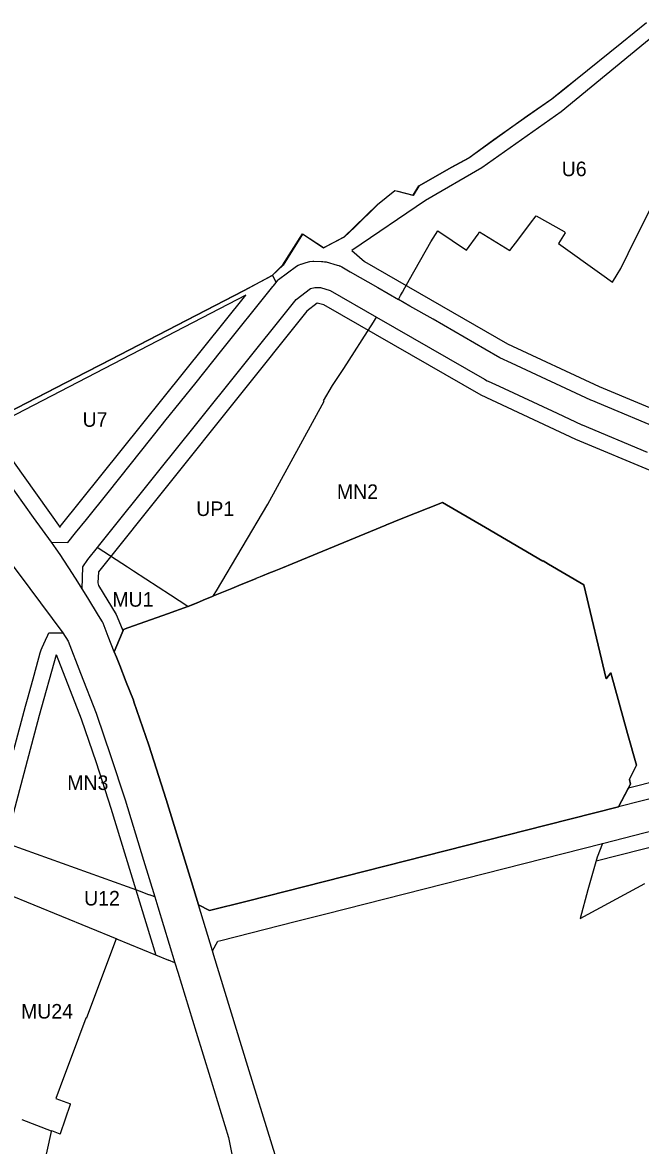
# Model space of a CAD drawing. Extents: x 7428103 to 7431580, y 5545880 to 5549002.
# Drawn here: x 7429328.8 to 7429564.3, y 5548288 to 5548716 of the extents above; entities that cross this region are included whole.
import ezdxf

# ---------------------------------------------------------------- set-up
doc = ezdxf.new("R2010")
doc.units = 0
for name, color, linetype in [('CZ_L_granica obszaru objętego planem', 7, 'Continuous'), ('CZ_L_linie rozgraniczające tereny o różnym przeznaczeniu oraz różnych warunkach ich zabudowy i zagospodarowania', 7, 'Continuous'), ('CZ_L_maksymalne nieprzekraczalne linie zabudowy', 7, 'Continuous'), ('CZ_L_opisy_linie rozgraniczające tereny o różnym przeznaczeniu oraz różnych warunkach ich zabudowy i zagospodarowania', 7, 'Continuous'), ('WYROK_NSA', 7, 'Continuous')]:
    doc.layers.add(name, color=color, linetype=linetype)

msp = doc.modelspace()

# ---------------------------------------------------------------- linework, layer by layer
at = {"layer": 'CZ_L_granica obszaru objętego planem'}
for p, q in [((7429557.12, 5548708.39), (7429566.53, 5548715.99)), ((7429539.52, 5548694.12), (7429557.12, 5548708.39)), ((7429535.35, 5548690.75), (7429539.52, 5548694.12)), ((7429530.54, 5548686.85), (7429535.35, 5548690.75)), ((7429521.16, 5548680.39), (7429530.54, 5548686.85)), ((7429508.43, 5548671.31), (7429521.16, 5548680.39)), ((7429498.88, 5548664.38), (7429508.43, 5548671.31)), ((7429492.26, 5548660.85), (7429498.88, 5548664.38)), ((7429479.83, 5548653.7), (7429492.26, 5548660.85)), ((7429464.07, 5548646.61), (7429470.73, 5548651.95)), ((7429470.73, 5548651.95), (7429471.79, 5548651.68)), ((7429471.79, 5548651.68), (7429477.67, 5548650.19)), ((7429477.67, 5548650.19), (7429479.83, 5548653.7)), ((7429455.38, 5548638.09), (7429464.07, 5548646.61)), ((7429451.42, 5548634.34), (7429455.38, 5548638.09)), ((7429428.08, 5548623.58), (7429435.53, 5548635.44)), ((7429435.53, 5548635.44), (7429443.48, 5548630.17)), ((7429443.48, 5548630.17), (7429451.42, 5548634.34)), ((7429424, 5548619.62), (7429428.08, 5548623.58)), ((7429413.14, 5548613.81), (7429424, 5548619.62)), ((7429358.68, 5548585.66), (7429413.14, 5548613.81)), ((7429315.24, 5548563.23), (7429352.99, 5548582.71)), ((7429352.99, 5548582.71), (7429358.68, 5548585.66))]:
    msp.add_line(p, q, dxfattribs=at)
at = {"layer": 'CZ_L_linie rozgraniczające tereny o różnym przeznaczeniu oraz różnych warunkach ich zabudowy i zagospodarowania'}
for p, q in [((7429559.62, 5548627.96), (7429570.43, 5548649.63)), ((7429522.39, 5548639.57), (7429524.57, 5548642.33)), ((7429524.57, 5548642.33), (7429535.16, 5548636.29)), ((7429517.91, 5548633.52), (7429522.39, 5548639.57)), ((7429484.44, 5548632.45), (7429487.04, 5548636.56)), ((7429487.04, 5548636.56), (7429497.94, 5548629.18)), ((7429497.94, 5548629.18), (7429502.46, 5548635.37)), ((7429502.46, 5548635.37), (7429503, 5548636.25)), ((7429503, 5548636.25), (7429514.56, 5548629.09)), ((7429514.56, 5548629.09), (7429517.91, 5548633.52)), ((7429535.55, 5548635.81), (7429533.08, 5548631.77)), ((7429535.16, 5548636.29), (7429535.49, 5548636.11)), ((7429535.49, 5548636.11), (7429535.55, 5548635.81)), ((7429476.24, 5548618.08), (7429484.44, 5548632.45)), ((7429533.08, 5548631.77), (7429549.51, 5548619.98)), ((7429436.91, 5548624.48), (7429438.36, 5548624.88)), ((7429438.36, 5548624.88), (7429439.48, 5548625.06)), ((7429439.48, 5548625.06), (7429439.69, 5548625.02)), ((7429439.69, 5548625.02), (7429439.86, 5548625.06)), ((7429439.86, 5548625.06), (7429442.75, 5548624.95)), ((7429442.75, 5548624.95), (7429443.31, 5548624.93)), ((7429443.31, 5548624.93), (7429443.94, 5548624.81)), ((7429443.94, 5548624.81), (7429444.52, 5548624.74)), ((7429444.52, 5548624.74), (7429448.78, 5548623.51)), ((7429556.78, 5548622.26), (7429559.62, 5548627.96)), ((7429426.43, 5548618.1), (7429433.26, 5548623.12)), ((7429433.26, 5548623.12), (7429433.86, 5548623.48)), ((7429433.26, 5548623.12), (7429433.26, 5548623.12)), ((7429433.86, 5548623.48), (7429434.18, 5548623.67)), ((7429434.18, 5548623.67), (7429434.94, 5548623.94)), ((7429434.94, 5548623.94), (7429434.96, 5548623.95)), ((7429434.96, 5548623.95), (7429436.91, 5548624.48)), ((7429448.78, 5548623.51), (7429449.34, 5548623.35)), ((7429449.34, 5548623.35), (7429449.48, 5548623.27)), ((7429449.48, 5548623.27), (7429449.68, 5548623.24)), ((7429449.68, 5548623.24), (7429450.45, 5548622.88)), ((7429450.45, 5548622.88), (7429453.69, 5548621.01)), ((7429453.69, 5548621.01), (7429464.24, 5548614.95)), ((7429555.36, 5548619.95), (7429556.78, 5548622.26)), ((7429424.05, 5548619.54), (7429425.49, 5548616.94)), ((7429424.45, 5548615.67), (7429425.47, 5548616.92)), ((7429425.47, 5548616.92), (7429425.49, 5548616.94)), ((7429425.49, 5548616.94), (7429426.17, 5548617.77)), ((7429426.17, 5548617.77), (7429426.43, 5548618.1)), ((7429474.45, 5548614.82), (7429476.24, 5548618.08)), ((7429549.51, 5548619.98), (7429553.58, 5548617.06)), ((7429553.58, 5548617.06), (7429555.36, 5548619.95)), ((7429404.26, 5548590.46), (7429424.17, 5548615.33)), ((7429424.17, 5548615.33), (7429424.45, 5548615.67)), ((7429433.11, 5548610.48), (7429438.52, 5548614.56)), ((7429438.52, 5548614.56), (7429440.27, 5548615.04)), ((7429440.27, 5548615.04), (7429442.33, 5548614.96)), ((7429442.33, 5548614.96), (7429445.99, 5548613.91)), ((7429445.99, 5548613.91), (7429463.74, 5548603.7)), ((7429464.24, 5548614.95), (7429472.06, 5548610.45)), ((7429472.06, 5548610.45), (7429472.86, 5548611.91)), ((7429472.86, 5548611.91), (7429473.58, 5548613.23)), ((7429473.58, 5548613.23), (7429474.45, 5548614.82)), ((7429394.23, 5548561.93), (7429431.08, 5548607.94)), ((7429431.08, 5548607.94), (7429433.11, 5548610.48)), ((7429476.42, 5548607.95), (7429472.06, 5548610.45)), ((7429485.24, 5548602.88), (7429476.42, 5548607.95)), ((7429462.53, 5548601.81), (7429463.74, 5548603.7)), ((7429463.74, 5548603.7), (7429504.89, 5548580.05)), ((7429458.28, 5548595.11), (7429462.53, 5548601.81)), ((7429505.03, 5548591.51), (7429485.24, 5548602.88)), ((7429455.33, 5548590.52), (7429458.28, 5548595.11)), ((7429394.96, 5548578.86), (7429404.26, 5548590.46)), ((7429451.2, 5548584.15), (7429455.33, 5548590.52)), ((7429510.71, 5548588.24), (7429505.03, 5548591.51)), ((7429515.14, 5548586.18), (7429510.71, 5548588.24)), ((7429545.41, 5548572.11), (7429515.14, 5548586.18)), ((7429446.99, 5548577.71), (7429451.2, 5548584.15)), ((7429383.05, 5548564.01), (7429394.96, 5548578.86)), ((7429443.5, 5548571.8), (7429446.99, 5548577.71)), ((7429504.89, 5548580.05), (7429505.92, 5548579.46)), ((7429505.92, 5548579.46), (7429506.21, 5548579.32)), ((7429506.21, 5548579.32), (7429506.3, 5548579.26)), ((7429506.3, 5548579.26), (7429510.44, 5548577.34)), ((7429510.44, 5548577.34), (7429532.52, 5548567.07)), ((7429422.28, 5548532.5), (7429443.75, 5548571.66)), ((7429443.62, 5548571.73), (7429443.5, 5548571.8)), ((7429443.75, 5548571.66), (7429443.62, 5548571.73)), ((7429546.06, 5548571.81), (7429545.41, 5548572.11)), ((7429547.85, 5548571.05), (7429546.06, 5548571.81)), ((7429575.56, 5548559.42), (7429547.85, 5548571.05)), ((7429532.52, 5548567.07), (7429541.93, 5548562.7)), ((7429361.42, 5548536.89), (7429382.17, 5548562.9)), ((7429381.32, 5548545.8), (7429394.23, 5548561.93)), ((7429382.17, 5548562.9), (7429383.05, 5548564.01)), ((7429541.93, 5548562.7), (7429542.08, 5548562.64)), ((7429542.08, 5548562.64), (7429542.1, 5548562.62)), ((7429542.1, 5548562.62), (7429566.86, 5548552.23)), ((7429333.08, 5548527.41), (7429309.64, 5548560.15)), ((7429357.84, 5548516.48), (7429381.32, 5548545.8)), ((7429353.19, 5548526.63), (7429361.42, 5548536.89)), ((7429402.7, 5548499.41), (7429422.28, 5548532.5)), ((7429473.1, 5548526.8), (7429488.81, 5548533.04)), ((7429488.81, 5548533.04), (7429505.19, 5548523.51)), ((7429339.85, 5548517.93), (7429333.08, 5548527.41)), ((7429349.06, 5548521.48), (7429353.19, 5548526.63)), ((7429467.54, 5548524.61), (7429473.1, 5548526.8)), ((7429437.47, 5548512.06), (7429467.28, 5548524.47)), ((7429467.28, 5548524.47), (7429467.42, 5548524.56)), ((7429467.42, 5548524.56), (7429467.48, 5548524.6)), ((7429467.48, 5548524.6), (7429467.51, 5548524.63)), ((7429467.51, 5548524.63), (7429467.54, 5548524.61)), ((7429505.19, 5548523.51), (7429527.05, 5548510.75)), ((7429341.64, 5548515.43), (7429339.85, 5548517.93)), ((7429339.85, 5548517.93), (7429346.14, 5548517.84)), ((7429346.14, 5548517.84), (7429349.06, 5548521.48)), ((7429319.88, 5548515.91), (7429331.62, 5548500.25)), ((7429343.2, 5548513.25), (7429341.64, 5548515.43)), ((7429353.71, 5548511.33), (7429357.37, 5548515.9)), ((7429357.37, 5548515.9), (7429357.84, 5548516.48)), ((7429357.72, 5548515.63), (7429357.37, 5548515.9)), ((7429368.82, 5548508.4), (7429357.72, 5548515.63)), ((7429347.94, 5548506.06), (7429343.2, 5548513.25)), ((7429351.78, 5548508.58), (7429353.71, 5548511.33)), ((7429427.83, 5548508.19), (7429431.53, 5548509.68)), ((7429431.53, 5548509.68), (7429431.63, 5548509.72)), ((7429431.63, 5548509.72), (7429437.47, 5548512.06)), ((7429527.05, 5548510.75), (7429527.15, 5548510.88)), ((7429527.15, 5548510.88), (7429529.27, 5548509.55)), ((7429529.27, 5548509.55), (7429542.72, 5548501.72)), ((7429349.9, 5548502.87), (7429347.94, 5548506.06)), ((7429351.54, 5548500.19), (7429351.78, 5548508.58)), ((7429371.12, 5548506.9), (7429368.82, 5548508.4)), ((7429385.23, 5548497.72), (7429371.12, 5548506.9)), ((7429417.84, 5548504.18), (7429420.26, 5548505.15)), ((7429420.26, 5548505.15), (7429422.65, 5548506.11)), ((7429422.65, 5548506.11), (7429424.77, 5548506.96)), ((7429424.77, 5548506.96), (7429427.83, 5548508.19)), ((7429351.54, 5548500.19), (7429349.9, 5548502.87)), ((7429408.58, 5548500.34), (7429412.14, 5548501.8)), ((7429412.14, 5548501.8), (7429415.1, 5548503.02)), ((7429415.1, 5548503.02), (7429417.85, 5548504.15)), ((7429417.85, 5548504.15), (7429417.84, 5548504.18)), ((7429542.72, 5548501.72), (7429551.2, 5548465.86)), ((7429331.62, 5548500.25), (7429344.19, 5548483.46)), ((7429353.68, 5548496.69), (7429351.54, 5548500.19)), ((7429357.74, 5548490.04), (7429353.68, 5548496.69)), ((7429391.86, 5548493.44), (7429385.23, 5548497.72)), ((7429401.5, 5548497.44), (7429401.61, 5548497.62)), ((7429401.5, 5548497.44), (7429401.6, 5548497.48)), ((7429401.6, 5548497.48), (7429402.18, 5548497.72)), ((7429401.61, 5548497.62), (7429401.65, 5548497.63)), ((7429401.65, 5548497.63), (7429402.7, 5548499.41)), ((7429402.18, 5548497.72), (7429408.58, 5548500.34)), ((7429384.04, 5548490.64), (7429391.85, 5548493.41)), ((7429391.85, 5548493.41), (7429391.86, 5548493.44)), ((7429359.27, 5548487.56), (7429357.74, 5548490.04)), ((7429369.03, 5548485.31), (7429382.25, 5548490.01)), ((7429382.25, 5548490.01), (7429384.04, 5548490.64)), ((7429338.93, 5548483.39), (7429344.19, 5548483.46)), ((7429344.19, 5548483.46), (7429346.2, 5548480.18)), ((7429359.57, 5548487.06), (7429359.27, 5548487.56)), ((7429361.52, 5548482.07), (7429359.57, 5548487.06)), ((7429366.8, 5548483.37), (7429367.36, 5548484.72)), ((7429367.36, 5548484.72), (7429369.03, 5548485.31)), ((7429336.32, 5548477.77), (7429337.57, 5548480.59)), ((7429337.57, 5548480.59), (7429338.47, 5548482.58)), ((7429338.47, 5548482.58), (7429338.93, 5548483.39)), ((7429346.2, 5548480.18), (7429350.9, 5548468.02)), ((7429363.82, 5548476.18), (7429361.52, 5548482.07)), ((7429363.82, 5548476.18), (7429366.8, 5548483.37)), ((7429333.23, 5548467.22), (7429335.62, 5548475.77)), ((7429335.62, 5548475.77), (7429335.95, 5548476.94)), ((7429335.95, 5548476.94), (7429336.32, 5548477.77)), ((7429364.61, 5548474.14), (7429363.82, 5548476.18)), ((7429365.87, 5548470.92), (7429364.61, 5548474.14)), ((7429368.36, 5548464.56), (7429365.87, 5548470.92)), ((7429330.95, 5548459.05), (7429333.23, 5548467.22)), ((7429350.9, 5548468.02), (7429356.89, 5548452.77)), ((7429551.2, 5548465.86), (7429552.92, 5548468.23)), ((7429552.92, 5548468.23), (7429559.36, 5548445.05)), ((7429371.1, 5548457.78), (7429368.36, 5548464.56)), ((7429329.96, 5548455.51), (7429330.95, 5548459.05)), ((7429371.28, 5548457.15), (7429371.1, 5548457.78)), ((7429325.56, 5548438.86), (7429329.96, 5548455.51)), ((7429376.91, 5548440.56), (7429371.28, 5548457.15)), ((7429356.89, 5548452.77), (7429357.03, 5548452.41)), ((7429357.03, 5548452.41), (7429357.14, 5548452.02)), ((7429357.14, 5548452.02), (7429362.38, 5548436.71)), ((7429559.36, 5548445.05), (7429562.71, 5548432.99)), ((7429362.38, 5548436.71), (7429367.93, 5548419.79)), ((7429383.57, 5548419.96), (7429376.91, 5548440.56)), ((7429624.89, 5548434.67), (7429555.85, 5548417.11)), ((7429562.71, 5548432.99), (7429560.09, 5548427.59)), ((7429549.78, 5548403.19), (7429637.98, 5548425.61)), ((7429560.52, 5548425.69), (7429555.85, 5548417.11)), ((7429560.06, 5548427.52), (7429560.04, 5548427.48)), ((7429560.04, 5548427.48), (7429560.52, 5548425.69)), ((7429560.09, 5548427.59), (7429560.06, 5548427.53)), ((7429560.06, 5548427.53), (7429560.06, 5548427.52)), ((7429367.93, 5548419.79), (7429375, 5548396.73)), ((7429393.2, 5548388.55), (7429383.57, 5548419.96)), ((7429555.85, 5548417.11), (7429528.33, 5548410.12)), ((7429528.33, 5548410.12), (7429513.3, 5548406.3)), ((7429373.74, 5548384.85), (7429316.88, 5548405.29)), ((7429513.3, 5548406.3), (7429443.95, 5548388.66)), ((7429444.36, 5548376.39), (7429549.78, 5548403.19)), ((7429549.78, 5548403.19), (7429547.82, 5548397.93)), ((7429547.82, 5548397.93), (7429544.18, 5548385.45)), ((7429375, 5548396.73), (7429379.25, 5548382.86)), ((7429395.87, 5548379.8), (7429393.2, 5548388.55)), ((7429443.95, 5548388.66), (7429414.41, 5548381.15)), ((7429541.3, 5548374.61), (7429565.87, 5548387.95)), ((7429544.18, 5548385.45), (7429541.3, 5548374.61)), ((7429377.21, 5548383.51), (7429373.74, 5548384.85)), ((7429379.25, 5548382.86), (7429377.18, 5548383.61)), ((7429377.18, 5548383.61), (7429377.21, 5548383.51)), ((7429379.25, 5548382.86), (7429380.42, 5548379.04)), ((7429414.41, 5548381.15), (7429400.08, 5548377.56)), ((7429380.42, 5548379.04), (7429386.93, 5548357.7)), ((7429401.23, 5548362.24), (7429395.87, 5548379.8)), ((7429400.08, 5548377.56), (7429395.87, 5548379.8)), ((7429404.39, 5548366.22), (7429432.67, 5548373.41)), ((7429432.67, 5548373.41), (7429444.36, 5548376.39)), ((7429401.23, 5548362.24), (7429403.32, 5548365.95)), ((7429403.32, 5548365.95), (7429404.39, 5548366.22)), ((7429401.77, 5548360.44), (7429401.23, 5548362.24)), ((7429414.75, 5548318.17), (7429401.77, 5548360.44)), ((7429386.93, 5548357.7), (7429388.02, 5548354.11)), ((7429388.02, 5548354.11), (7429395.02, 5548331.3)), ((7429395.02, 5548331.3), (7429400.35, 5548313.95)), ((7429423.96, 5548288.2), (7429414.75, 5548318.17)), ((7429400.35, 5548313.95), (7429407.37, 5548291.1)), ((7429339.94, 5548293.49), (7429328.77, 5548297.85)), ((7429335.47, 5548273.67), (7429339.93, 5548293.42)), ((7429339.93, 5548293.42), (7429339.94, 5548293.49)), ((7429407.37, 5548291.1), (7429410.76, 5548273.99)), ((7429426.99, 5548278.37), (7429423.96, 5548288.2))]:
    msp.add_line(p, q, dxfattribs=at)
for points in [[(7429566.55, 5548715.89), (7429557.13, 5548708.28), (7429539.53, 5548694.02), (7429535.37, 5548690.64), (7429530.55, 5548686.75), (7429521.17, 5548680.28), (7429508.44, 5548671.21), (7429498.89, 5548664.28), (7429492.28, 5548660.74), (7429479.85, 5548653.6), (7429477.69, 5548650.08), (7429471.8, 5548651.58), (7429470.74, 5548651.84), (7429464.08, 5548646.5), (7429455.39, 5548637.98), (7429451.43, 5548634.24), (7429443.49, 5548630.06), (7429435.54, 5548635.33), (7429428.09, 5548623.47), (7429424.02, 5548619.52), (7429413.15, 5548613.7), (7429358.69, 5548585.55), (7429353, 5548582.61), (7429315.25, 5548563.12)], [(7429391.86, 5548493.44), (7429391.91, 5548493.44), (7429395.38, 5548494.89), (7429398.51, 5548496.19), (7429401.5, 5548497.44)], [(7429391.86, 5548493.44), (7429391.86, 5548493.44)], [(7429311.75, 5548388.53), (7429311.92, 5548388.46), (7429364.74, 5548366.81), (7429364.8, 5548366.69)], [(7429364.8, 5548366.68), (7429364.56, 5548366.78), (7429353.17, 5548336.76), (7429353.18, 5548336.53), (7429353.02, 5548336.6), (7429347.38, 5548321.65), (7429344.45, 5548313.86), (7429341.48, 5548305.99), (7429347.09, 5548303.97), (7429347.05, 5548303.86), (7429347.01, 5548303.73), (7429343.2, 5548292.46), (7429343.19, 5548292.43), (7429343.19, 5548292.42), (7429343.19, 5548292.42), (7429339.97, 5548293.62), (7429339.94, 5548293.49)], [(7429386.93, 5548357.7), (7429384.52, 5548358.63), (7429384.54, 5548358.54), (7429364.81, 5548366.68), (7429364.8, 5548366.69)], [(7429364.81, 5548366.68), (7429364.8, 5548366.68)], [(7429364.8, 5548366.68), (7429364.8, 5548366.68)]]:
    msp.add_lwpolyline(points, dxfattribs=at)
at = {"layer": 'CZ_L_maksymalne nieprzekraczalne linie zabudowy'}
for points in [[(7429572.8, 5548715.52), (7429571.94, 5548713.05), (7429534.01, 5548681.96), (7429503.84, 5548660.58), (7429482.42, 5548648.2), (7429454.26, 5548629.06)], [(7429454.26, 5548629.06), (7429459.09, 5548624.93), (7429513.62, 5548593.5), (7429548.5, 5548577.29), (7429582.33, 5548563.17)], [(7429343.23, 5548523.88), (7429413.91, 5548612.11), (7429316.15, 5548561.37), (7429343.22, 5548523.54)], [(7429715.23, 5548499.33), (7429715.47, 5548504.35), (7429717.27, 5548522.67), (7429718.08, 5548529.18), (7429718.01, 5548529.54), (7429716.73, 5548531.32), (7429693.9, 5548535.08), (7429681.78, 5548536.15), (7429666.49, 5548536.47), (7429592.48, 5548539.29), (7429582.27, 5548540.62), (7429576.21, 5548542.01), (7429569.46, 5548544.64), (7429539.67, 5548557.14), (7429503.52, 5548573.95), (7429443.6, 5548608.35), (7429441.12, 5548609), (7429437.2, 5548605.98), (7429357.8, 5548506.71), (7429357.6, 5548502.44), (7429357.83, 5548501.41), (7429364.53, 5548490.43), (7429366.81, 5548484.98)], [(7429367.13, 5548484.17), (7429366.81, 5548484.98), (7429367.13, 5548484.17)], [(7429341.66, 5548475.02), (7429335.21, 5548451.88), (7429320.74, 5548397.16), (7429310.09, 5548363.49), (7429299.06, 5548334.66), (7429287.9, 5548308.54), (7429279.42, 5548283.92), (7429270.71, 5548265.21)], [(7429379.79, 5548360.52), (7429362.68, 5548416.45), (7429357.01, 5548433.82), (7429351.35, 5548450.46), (7429341.78, 5548474.97)], [(7429559.77, 5548424.31), (7429617.45, 5548438.97)], [(7429644.04, 5548420.97), (7429547.33, 5548396.38)]]:
    msp.add_lwpolyline(points, dxfattribs=at)
at = {"layer": 'WYROK_NSA'}
for p, q in [((7429488.81, 5548533.04), (7429473.1, 5548526.8)), ((7429505.19, 5548523.51), (7429488.81, 5548533.04)), ((7429473.1, 5548526.8), (7429467.54, 5548524.61)), ((7429467.28, 5548524.47), (7429437.47, 5548512.06)), ((7429467.42, 5548524.56), (7429467.28, 5548524.47)), ((7429467.54, 5548524.61), (7429467.42, 5548524.56)), ((7429527.05, 5548510.75), (7429505.19, 5548523.51)), ((7429431.53, 5548509.68), (7429427.83, 5548508.19)), ((7429431.63, 5548509.72), (7429431.53, 5548509.68)), ((7429437.47, 5548512.06), (7429431.63, 5548509.72)), ((7429527.15, 5548510.88), (7429527.05, 5548510.75)), ((7429529.27, 5548509.55), (7429527.15, 5548510.88)), ((7429542.72, 5548501.72), (7429529.27, 5548509.55)), ((7429420.26, 5548505.15), (7429417.85, 5548504.15)), ((7429422.65, 5548506.11), (7429420.26, 5548505.15)), ((7429424.77, 5548506.96), (7429422.65, 5548506.11)), ((7429427.83, 5548508.19), (7429424.77, 5548506.96)), ((7429412.14, 5548501.8), (7429408.58, 5548500.34)), ((7429415.1, 5548503.02), (7429412.14, 5548501.8)), ((7429417.85, 5548504.15), (7429415.1, 5548503.02)), ((7429551.2, 5548465.86), (7429542.72, 5548501.72)), ((7429401.5, 5548497.44), (7429398.51, 5548496.19)), ((7429402.18, 5548497.72), (7429401.5, 5548497.44)), ((7429408.58, 5548500.34), (7429402.18, 5548497.72)), ((7429391.85, 5548493.41), (7429384.04, 5548490.64)), ((7429382.25, 5548490.01), (7429369.03, 5548485.31)), ((7429384.04, 5548490.64), (7429382.25, 5548490.01)), ((7429369.03, 5548485.31), (7429367.36, 5548484.72)), ((7429366.8, 5548483.37), (7429363.82, 5548476.18)), ((7429363.82, 5548476.18), (7429364.61, 5548474.14)), ((7429364.61, 5548474.14), (7429365.87, 5548470.92)), ((7429365.87, 5548470.92), (7429368.36, 5548464.56)), ((7429552.92, 5548468.23), (7429551.2, 5548465.86)), ((7429559.36, 5548445.05), (7429552.92, 5548468.23)), ((7429368.36, 5548464.56), (7429371.1, 5548457.78)), ((7429371.1, 5548457.78), (7429371.28, 5548457.15)), ((7429371.28, 5548457.15), (7429376.91, 5548440.56)), ((7429562.71, 5548432.99), (7429559.36, 5548445.05)), ((7429376.91, 5548440.56), (7429383.57, 5548419.96)), ((7429560.09, 5548427.59), (7429562.71, 5548432.99)), ((7429560.06, 5548427.53), (7429560.09, 5548427.59)), ((7429560.52, 5548425.69), (7429560.06, 5548427.53)), ((7429383.57, 5548419.96), (7429393.2, 5548388.55)), ((7429528.33, 5548410.12), (7429555.85, 5548417.11)), ((7429513.3, 5548406.3), (7429528.33, 5548410.12)), ((7429443.95, 5548388.66), (7429513.3, 5548406.3)), ((7429393.2, 5548388.55), (7429395.87, 5548379.8)), ((7429414.41, 5548381.15), (7429443.95, 5548388.66)), ((7429400.08, 5548377.56), (7429414.41, 5548381.15)), ((7429395.87, 5548379.8), (7429400.08, 5548377.56))]:
    msp.add_line(p, q, dxfattribs=at)
for points in [[(7429398.51, 5548496.19), (7429395.38, 5548494.89), (7429391.85, 5548493.41)], [(7429367.36, 5548484.72), (7429367.13, 5548484.17), (7429366.8, 5548483.37)], [(7429555.85, 5548417.11), (7429559.77, 5548424.31), (7429560.52, 5548425.69)]]:
    msp.add_lwpolyline(points, dxfattribs=at)

# ---------------------------------------------------------------- texts
at = {"layer": 'CZ_L_opisy_linie rozgraniczające tereny o różnym przeznaczeniu oraz różnych warunkach ich zabudowy i zagospodarowania'}
for s, p in [('U6', (7429534.26, 5548657.42)), ('U7', (7429351.73, 5548561.93)), ('MN2', (7429448.62, 5548534.42)), ('UP1', (7429395.03, 5548527.93)), ('MU1', (7429363.08, 5548493.36)), ('MN3', (7429345.89, 5548423.53)), ('U12', (7429352.32, 5548379.51)), ('MU24', (7429328.28, 5548336.42))]:
    msp.add_text(s, height=5.549, dxfattribs=at).set_placement(p)

doc.saveas('drawing.dxf')
